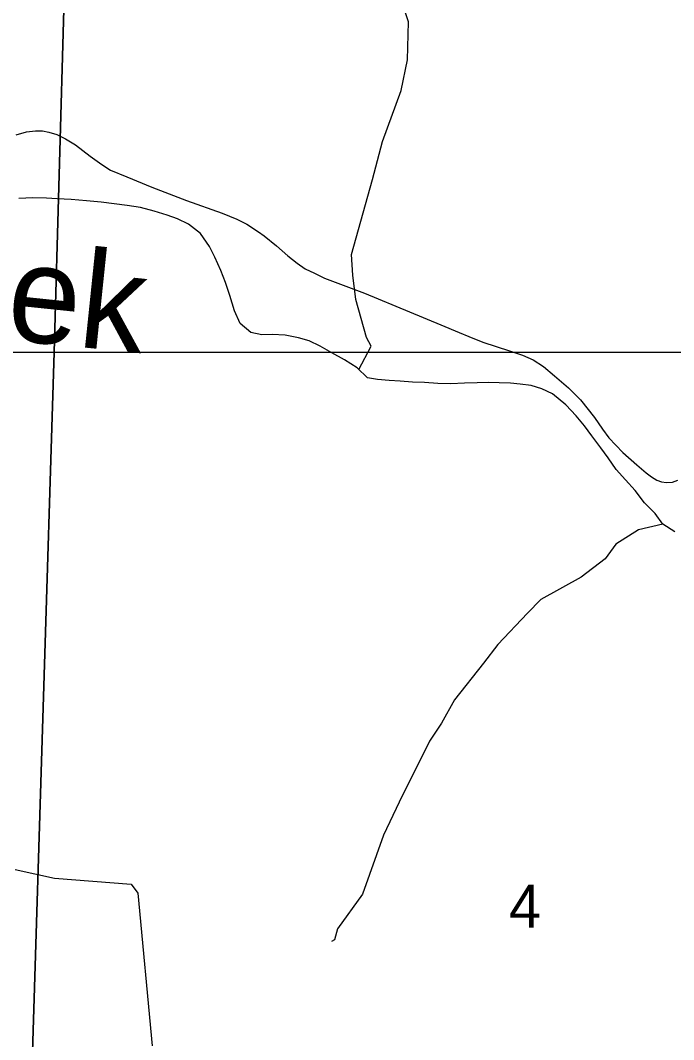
# Model space of a CAD drawing. Extents: x 2.1 to 8.9, y 14.1 to 20.9.
# Drawn here: x 5.459 to 6.096, y 16.441 to 17.436 of the extents above; entities that cross this region are included whole.
import ezdxf

# ---------------------------------------------------------------- set-up
doc = ezdxf.new("R2010")
doc.units = 0
for name, color, linetype in [('GM_X_City_Street', 7, 'Continuous'), ('GM_X_County_Road_Text', 7, 'Continuous'), ('GM_X_Interchange_Ramps', 7, 'Continuous'), ('GM_X_State_Shield', 7, 'Continuous'), ('PV_P_Text', 7, 'Continuous'), ('TX_P_Misc', 7, 'Continuous')]:
    doc.layers.add(name, color=color, linetype=linetype)

msp = doc.modelspace()

# ---------------------------------------------------------------- linework, layer by layer
at = {"layer": 'GM_X_City_Street'}
for p, q in [((5.45375, 16.60731), (5.49216, 16.59855)), ((5.49216, 16.59855), (5.56685, 16.59274)), ((5.56685, 16.59274), (5.57348, 16.58399)), ((5.57348, 16.58399), (5.58745, 16.43507))]:
    msp.add_line(p, q, dxfattribs=at)
at = {"layer": 'GM_X_Interchange_Ramps'}
for p, q in [((5.51984, 18.10239), (5.49195, 17.11174)), ((5.49195, 17.11174), (5.51984, 18.10239)), ((5.49195, 17.11174), (4.49279, 17.10988)), ((4.49279, 17.10988), (5.49195, 17.11174)), ((5.49195, 17.11174), (5.45975, 16.07174)), ((5.45975, 16.07174), (5.49195, 17.11174)), ((6.43657, 17.11137), (5.49195, 17.11174)), ((5.49195, 17.11174), (6.43657, 17.11137))]:
    msp.add_line(p, q, dxfattribs=at)
at = {"layer": 'GM_X_State_Shield'}
for p, q in [((5.45476, 17.32376), (5.46498, 17.32677)), ((5.46498, 17.32677), (5.47353, 17.32795)), ((5.47353, 17.32795), (5.48056, 17.32778)), ((5.48056, 17.32778), (5.48676, 17.32661)), ((5.48676, 17.32661), (5.4943, 17.32426)), ((5.4943, 17.32426), (5.50301, 17.32007)), ((5.50301, 17.32007), (5.51273, 17.31421)), ((5.51273, 17.31421), (5.52697, 17.30298)), ((5.52697, 17.30298), (5.5382, 17.29494)), ((5.5382, 17.29494), (5.54674, 17.28941)), ((5.54674, 17.28941), (5.56282, 17.28288)), ((5.56282, 17.28288), (5.58712, 17.27283)), ((5.58712, 17.27283), (5.62096, 17.25992)), ((5.62096, 17.25992), (5.65581, 17.24753)), ((5.65581, 17.24753), (5.66988, 17.2415)), ((5.66988, 17.2415), (5.67977, 17.2368)), ((5.67977, 17.2368), (5.69099, 17.22926)), ((5.69099, 17.22926), (5.69652, 17.22524)), ((5.69652, 17.22524), (5.70875, 17.21569)), ((5.70875, 17.21569), (5.71981, 17.20581)), ((5.71981, 17.20581), (5.72886, 17.19877)), ((5.72886, 17.19877), (5.73673, 17.19324)), ((5.73673, 17.19324), (5.74561, 17.18889)), ((5.74561, 17.18889), (5.7555, 17.1842)), ((5.7555, 17.1842), (5.79437, 17.16929)), ((5.79437, 17.16929), (5.83843, 17.15136)), ((5.83843, 17.15136), (5.86892, 17.13863)), ((5.86892, 17.13863), (5.88668, 17.13109)), ((5.88668, 17.13109), (5.89623, 17.12706)), ((5.89623, 17.12706), (5.90997, 17.12154)), ((5.90997, 17.12154), (5.93594, 17.11333)), ((5.93594, 17.11333), (5.9485, 17.10897)), ((5.9485, 17.10897), (5.95889, 17.10445)), ((5.95889, 17.10445), (5.96894, 17.09791)), ((5.96894, 17.09791), (5.97983, 17.08887)), ((5.97983, 17.08887), (5.99357, 17.07697)), ((5.99357, 17.07697), (6.0053, 17.06524)), ((6.0053, 17.06524), (6.01887, 17.04799)), ((6.01887, 17.04799), (6.02674, 17.03676)), ((6.02674, 17.03676), (6.03277, 17.02822)), ((6.03277, 17.02822), (6.03964, 17.02118)), ((6.03964, 17.02118), (6.04651, 17.01414)), ((6.04651, 17.01414), (6.06025, 17.00208)), ((6.06025, 17.00208), (6.06913, 16.99421)), ((6.06913, 16.99421), (6.07432, 16.99018)), ((6.07432, 16.99018), (6.07952, 16.987)), ((6.07952, 16.987), (6.08404, 16.98549)), ((6.08404, 16.98549), (6.08907, 16.98482)), ((6.08907, 16.98482), (6.09493, 16.98516)), ((6.09493, 16.98516), (6.09996, 16.987))]:
    msp.add_line(p, q, dxfattribs=at)
at = {"layer": 'TX_P_Misc'}
for p, q in [((5.83743, 17.43403), (5.82626, 17.46888)), ((5.83655, 17.39709), (5.83743, 17.43403)), ((5.83025, 17.36728), (5.83655, 17.39709)), ((5.81219, 17.31748), (5.83025, 17.36728)), ((5.80224, 17.28038), (5.81219, 17.31748)), ((5.78193, 17.20732), (5.80224, 17.28038)), ((5.47086, 17.26259), (5.4572, 17.26178)), ((5.48418, 17.26225), (5.47086, 17.26259)), ((5.49485, 17.26144), (5.48418, 17.26225)), ((5.50856, 17.26073), (5.49485, 17.26144)), ((5.52342, 17.25967), (5.50856, 17.26073)), ((5.53753, 17.2582), (5.52342, 17.25967)), ((5.56311, 17.25482), (5.53753, 17.2582)), ((5.57609, 17.25294), (5.56311, 17.25482)), ((5.5895, 17.24955), (5.57609, 17.25294)), ((5.60217, 17.24538), (5.5895, 17.24955)), ((5.61217, 17.24188), (5.60217, 17.24538)), ((5.62296, 17.23689), (5.61217, 17.24188)), ((5.63465, 17.22773), (5.62296, 17.23689)), ((5.6434, 17.21505), (5.63465, 17.22773)), ((5.64866, 17.20455), (5.6434, 17.21505)), ((5.65439, 17.1914), (5.64866, 17.20455)), ((5.78303, 17.18716), (5.78193, 17.20732)), ((5.65892, 17.17973), (5.65439, 17.1914)), ((5.78608, 17.16322), (5.78303, 17.18716)), ((5.66311, 17.16729), (5.65892, 17.17973)), ((5.66775, 17.1522), (5.66311, 17.16729)), ((5.79654, 17.12607), (5.78608, 17.16322)), ((5.67307, 17.1398), (5.66775, 17.1522)), ((5.6836, 17.13099), (5.67307, 17.1398)), ((5.69432, 17.12866), (5.6836, 17.13099)), ((5.70457, 17.12898), (5.69432, 17.12866)), ((5.71713, 17.12861), (5.70457, 17.12898)), ((5.73014, 17.12597), (5.71713, 17.12861)), ((5.7405, 17.12286), (5.73014, 17.12597)), ((5.80084, 17.11777), (5.79654, 17.12607)), ((5.75129, 17.11787), (5.7405, 17.12286)), ((5.76252, 17.11136), (5.75129, 17.11787)), ((5.78894, 17.09498), (5.80084, 17.11777)), ((5.77489, 17.10451), (5.76252, 17.11136)), ((5.7873, 17.09652), (5.77489, 17.10451)), ((5.79748, 17.08693), (5.7873, 17.09652)), ((5.80703, 17.08533), (5.79748, 17.08693)), ((5.81847, 17.08416), (5.80703, 17.08533)), ((5.82913, 17.08374), (5.81847, 17.08416)), ((5.84133, 17.08259), (5.82913, 17.08374)), ((5.85313, 17.0822), (5.84133, 17.08259)), ((5.86608, 17.08146), (5.85313, 17.0822)), ((5.87863, 17.0811), (5.86608, 17.08146)), ((5.89193, 17.08151), (5.87863, 17.0811)), ((5.90446, 17.0819), (5.89193, 17.08151)), ((5.91548, 17.08225), (5.90446, 17.0819)), ((5.92576, 17.08181), (5.91548, 17.08225)), ((5.93678, 17.08177), (5.92576, 17.08181)), ((5.94633, 17.08055), (5.93678, 17.08177)), ((5.95701, 17.07936), (5.94633, 17.08055)), ((5.96737, 17.07625), (5.95701, 17.07936)), ((5.97778, 17.07125), (5.96737, 17.07625)), ((5.99103, 17.06061), (5.97778, 17.07125)), ((6.00086, 17.04987), (5.99103, 17.06061)), ((6.00915, 17.03985), (6.00086, 17.04987)), ((6.01629, 17.03017), (6.00915, 17.03985)), ((6.02501, 17.01863), (6.01629, 17.03017)), ((6.03215, 17.00895), (6.02501, 17.01863)), ((6.0401, 16.99739), (6.03215, 17.00895)), ((6.04915, 16.98739), (6.0401, 16.99739)), ((6.05859, 16.97701), (6.04915, 16.98739)), ((6.06771, 16.96473), (6.05859, 16.97701)), ((6.07791, 16.95438), (6.06771, 16.96473)), ((6.08545, 16.94395), (6.07791, 16.95438)), ((6.06167, 16.93853), (6.03961, 16.92446)), ((6.08545, 16.94395), (6.06167, 16.93853)), ((6.09708, 16.93669), (6.08545, 16.94395)), ((6.03961, 16.92446), (6.02927, 16.9102)), ((6.02927, 16.9102), (6.00576, 16.8923)), ((6.00576, 16.8923), (5.96644, 16.87071)), ((5.96644, 16.87071), (5.95344, 16.85717)), ((5.95344, 16.85717), (5.92447, 16.82662)), ((5.92447, 16.82662), (5.91042, 16.80849)), ((5.91042, 16.80849), (5.8823, 16.77262)), ((5.8823, 16.77262), (5.86946, 16.74995)), ((5.86946, 16.74995), (5.85804, 16.73225)), ((5.85804, 16.73225), (5.82844, 16.67276)), ((5.82844, 16.67276), (5.81312, 16.64054)), ((5.81312, 16.64054), (5.79256, 16.58311)), ((5.79256, 16.58311), (5.7682, 16.54921)), ((5.7682, 16.54921), (5.76536, 16.53851)), ((5.76536, 16.53851), (5.76236, 16.53694))]:
    msp.add_line(p, q, dxfattribs=at)

# ---------------------------------------------------------------- texts
at = {"layer": 'GM_X_County_Road_Text'}
msp.add_text('4', height=0.04186, rotation=0.00001, dxfattribs=at).set_placement((5.93547, 16.55054))
at = {"layer": 'PV_P_Text'}
msp.add_text('Creek', height=0.0947, rotation=354.0791, dxfattribs=at).set_placement((5.24042, 17.14555))

doc.saveas('drawing.dxf')
